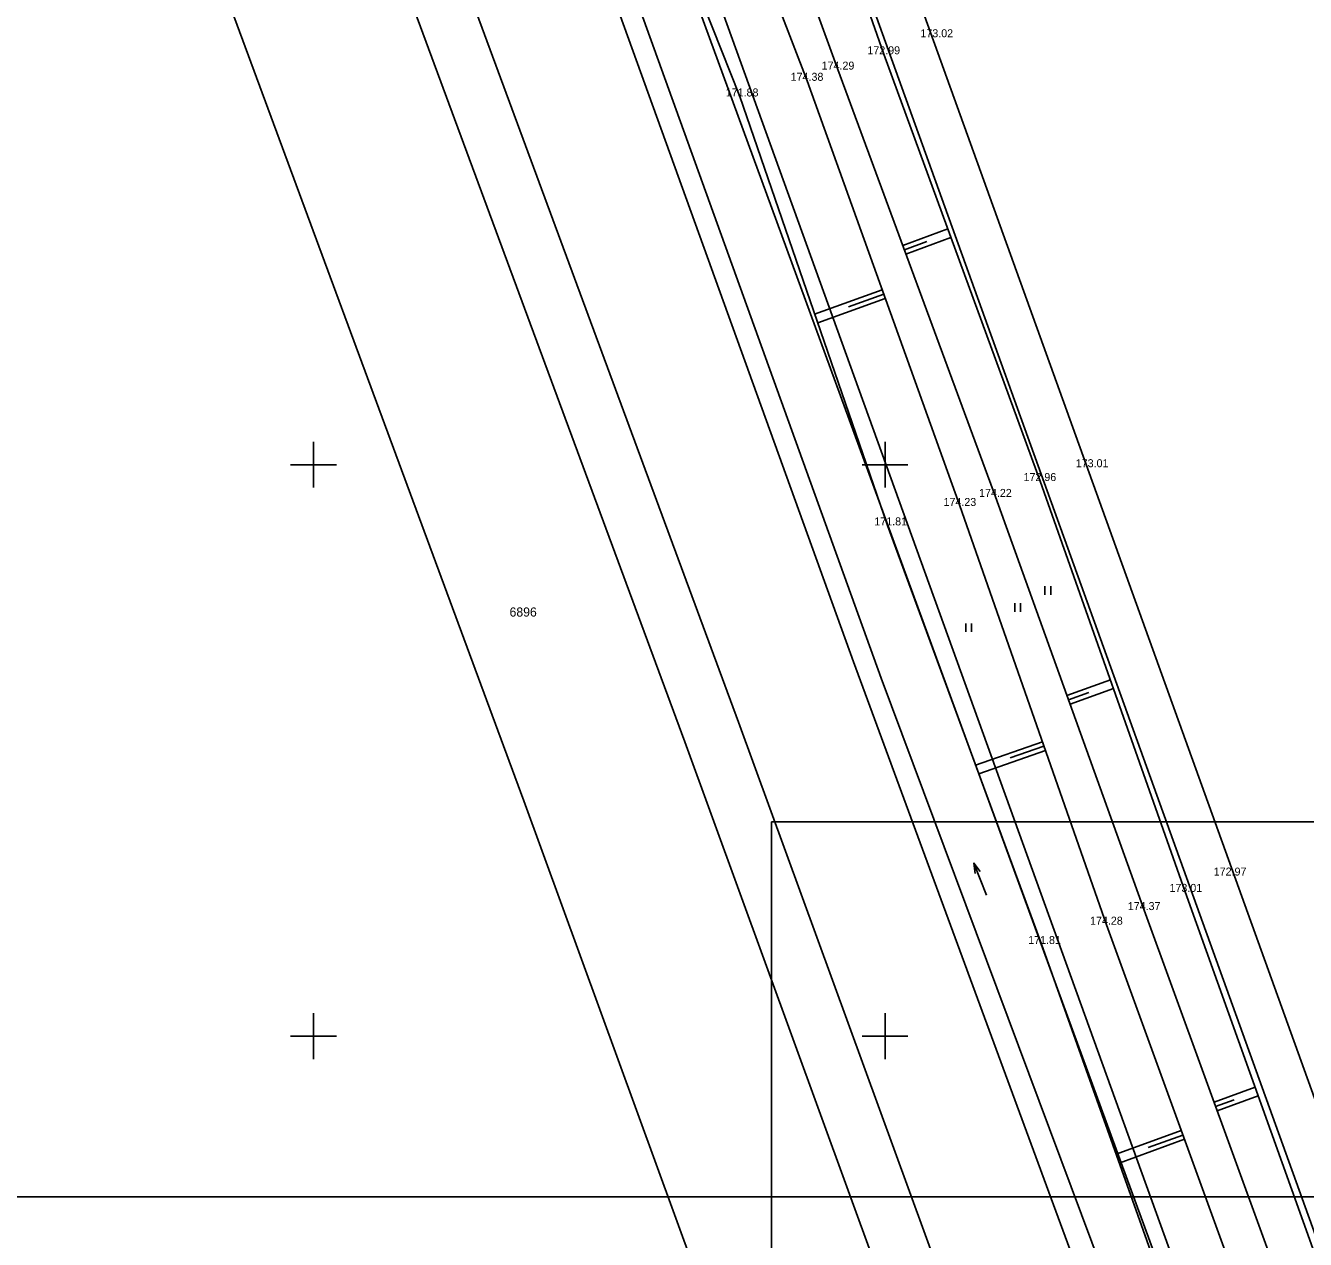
# Model space of a CAD drawing. Extents: x -612546 to -611926, y -1201932 to -1200444.
# Drawn here: x -612425.2 to -612313.2, y -1200867.8 to -1200761.6 of the extents above; entities that cross this region are included whole.
import ezdxf

# ---------------------------------------------------------------- set-up
doc = ezdxf.new("R2010")
doc.units = 0
for name, color, linetype in [('14 hrana pata svahu', 7, 'Continuous'), ('15 šrafy', 7, 'Continuous'), ('61 legenda křížky', 7, 'Continuous'), ('Hranice parcel', 7, 'Continuous'), ('Parcelní čísla', 7, 'Continuous'), ('Vnitřní kresba', 7, 'Continuous'), ('Vrstva 36', 7, 'Continuous'), ('Vrstva 45', 7, 'Continuous'), ('Vrstva 63', 7, 'Continuous'), ('výška bodu', 7, 'Continuous')]:
    doc.layers.add(name, color=color, linetype=linetype)

msp = doc.modelspace()

# ---------------------------------------------------------------- linework, layer by layer
at = {"layer": '14 hrana pata svahu'}
for points in [[(-612314.18, -1200875.11), (-612327.34, -1200838.97), (-612340.35, -1200802.82), (-612354.12, -1200765.43), (-612365.98, -1200732.87), (-612379.97, -1200693.65), (-612390.48, -1200664.58), (-612404.32, -1200627.17), (-612417.23, -1200591.7), (-612430.62, -1200555.12), (-612438.2, -1200533.09), (-612444.43, -1200520.21), (-612457.3, -1200503.64), (-612467.57, -1200490.07), (-612474.64, -1200478.9), (-612480.36, -1200469.57)], [(-612115.84, -1201111.42), (-612142.3, -1201080.92), (-612162.58, -1201054.92), (-612187.22, -1201025.94), (-612211.45, -1200996.73), (-612237.71, -1200968.13), (-612275.47, -1200925.26), (-612297.25, -1200898.18), (-612305.42, -1200888.34), (-612310.59, -1200874.11), (-612323.74, -1200837.38), (-612336.44, -1200801.43), (-612350.12, -1200764.09), (-612361.57, -1200731.35), (-612377.95, -1200692.77), (-612388.38, -1200663.69), (-612401.66, -1200625.89), (-612414.44, -1200590.59), (-612427.78, -1200553.92), (-612436.33, -1200532.1), (-612442.76, -1200519.02), (-612455.83, -1200502.43), (-612463.71, -1200487.36), (-612471.87, -1200478.15)], [(-612323.51, -1200877.98), (-612336.33, -1200841.94), (-612349.79, -1200805.31), (-612362.71, -1200767.78), (-612375.47, -1200735.58), (-612389.68, -1200697.07), (-612400.23, -1200666.93), (-612413.57, -1200629.83), (-612426, -1200594.78), (-612439.47, -1200557.74), (-612446.83, -1200536.72), (-612452.68, -1200524.51), (-612464.9, -1200509.43), (-612478.9, -1200492.91), (-612482.95, -1200488.23)], [(-612103.83, -1201136.8), (-612121.3, -1201116.23), (-612147.17, -1201085.43), (-612168.95, -1201059.31), (-612192.84, -1201031.05), (-612217.78, -1201001.78), (-612242.41, -1200972.81), (-612279.4, -1200929.44), (-612302.66, -1200902.78), (-612311.18, -1200891.48), (-612317.69, -1200875.87), (-612330.64, -1200840.25), (-612343.46, -1200803.61), (-612356.83, -1200766.41), (-612369.51, -1200733.46), (-612383.93, -1200694.82), (-612394.68, -1200665.1), (-612407.78, -1200627.56), (-612420.74, -1200592.57), (-612433.93, -1200555.79), (-612441.34, -1200534.1), (-612447.31, -1200522.04), (-612459.97, -1200505.78), (-612472.95, -1200489.44)]]:
    msp.add_lwpolyline(points, dxfattribs=at)
at = {"layer": '15 šrafy'}
for p, q in [((-612344.52, -1200779.37), (-612348.45, -1200780.82)), ((-612346.34, -1200780.47), (-612348.31, -1200781.19)), ((-612344.25, -1200780.12), (-612348.18, -1200781.57)), ((-612356.16, -1200786.82), (-612350.26, -1200784.7)), ((-612353.19, -1200786.18), (-612350.12, -1200785.08)), ((-612355.89, -1200787.58), (-612349.99, -1200785.45)), ((-612330.29, -1200818.83), (-612334.09, -1200820.2)), ((-612330.02, -1200819.59), (-612333.82, -1200820.96)), ((-612332.17, -1200819.94), (-612333.96, -1200820.58)), ((-612342.08, -1200826.29), (-612336.24, -1200824.25)), ((-612341.8, -1200827.04), (-612335.98, -1200825)), ((-612339.05, -1200825.65), (-612336.11, -1200824.62)), ((-612317.62, -1200854.47), (-612321.22, -1200855.78)), ((-612319.46, -1200855.57), (-612321.08, -1200856.16)), ((-612317.35, -1200855.23), (-612320.94, -1200856.54)), ((-612329.78, -1200860.34), (-612324.09, -1200858.27)), ((-612329.52, -1200861.1), (-612323.82, -1200859.02)), ((-612326.98, -1200859.75), (-612323.95, -1200858.65))]:
    msp.add_line(p, q, dxfattribs=at)
at = {"layer": '61 legenda křížky'}
for p, q in [((-612400, -1200802), (-612400, -1200798)), ((-612350, -1200802), (-612350, -1200798)), ((-612402, -1200800), (-612398, -1200800)), ((-612352, -1200800), (-612348, -1200800)), ((-612400, -1200852), (-612400, -1200848)), ((-612350, -1200852), (-612350, -1200848)), ((-612402, -1200850), (-612398, -1200850)), ((-612352, -1200850), (-612348, -1200850))]:
    msp.add_line(p, q, dxfattribs=at)
at = {"layer": 'Hranice parcel'}
for points in [[(-612492.54, -1200475.45), (-612489.15, -1200479.9), (-612487.29, -1200482.34), (-612470.55, -1200499.86), (-612454.58, -1200517.89), (-612449.12, -1200526.98), (-612444.88, -1200537.01), (-612400.71, -1200658.68), (-612382.76, -1200708.97), (-612320.94, -1200880.21), (-612316.28, -1200891.06), (-612307.37, -1200903.62), (-612259.67, -1200958.71), (-612214.29, -1201012.03), (-612172.62, -1201060.98), (-612120.7, -1201123.05), (-612073.85, -1201178.4), (-612068.4, -1201184.83), (-612055.42, -1201199.11), (-612044.78, -1201213.9), (-612040.42, -1201224.33), (-612036.87, -1201232.26)], [(-612053.63, -1201234.04), (-612049.72, -1201229.74), (-612051.31, -1201220.57), (-612058.28, -1201208.42), (-612073.89, -1201189.58), (-612079.31, -1201183.16), (-612173.25, -1201072.99), (-612266.53, -1200963.98), (-612308.11, -1200916.05), (-612320.05, -1200901.46), (-612326.37, -1200888.91), (-612352.76, -1200817.26), (-612383.45, -1200732.24), (-612424.46, -1200618.96), (-612450.75, -1200547.77), (-612455.75, -1200534.91), (-612462.05, -1200524.68), (-612490.01, -1200492.58), (-612497.19, -1200482.99)], [(-612504.85, -1200495.41), (-612492.66, -1200506.93), (-612476.27, -1200525), (-612462.43, -1200549.41), (-612435.01, -1200623.69), (-612394.62, -1200736.44), (-612362.83, -1200822.52), (-612336.91, -1200893.7), (-612329.46, -1200906.86), (-612317.29, -1200922.46), (-612274.72, -1200972.15), (-612181.97, -1201080.59), (-612092.56, -1201185.28), (-612096.16, -1201188.77)], [(-612098.55, -1201185.97), (-612185.77, -1201083.84), (-612278.52, -1200975.4), (-612321.16, -1200925.63), (-612333.63, -1200909.64), (-612341.47, -1200895.8), (-612367.52, -1200824.24), (-612399.32, -1200738.15), (-612439.71, -1200625.4), (-612466.98, -1200551.52), (-612480.35, -1200527.95), (-612496.23, -1200510.43), (-612507.54, -1200499.75)], [(-612424.14, -1200544.19), (-612385.56, -1200652.97), (-612376.97, -1200665.68), (-612365.31, -1200671.92), (-612359.59, -1200681.01), (-612363.6, -1200702.67), (-612362.5, -1200716.42), (-612304.9, -1200876.31), (-612299.88, -1200886.48), (-612289.63, -1200899.21), (-612225.19, -1200972.6)], [(-612480.63, -1200557.86), (-612453.81, -1200630.53), (-612413.42, -1200743.28), (-612381.61, -1200829.41), (-612355.13, -1200902.11), (-612346.14, -1200918), (-612332.78, -1200935.12), (-612289.91, -1200985.15), (-612197.17, -1201093.58), (-612109.96, -1201195.71)], [(-612367.63, -1200702.46), (-612366.44, -1200717.27), (-612308.59, -1200877.88), (-612303.27, -1200888.65), (-612292.69, -1200901.79), (-612203.37, -1201003.51), (-612163.72, -1201050.75), (-612139.89, -1201080.24), (-612084.23, -1201147.54), (-612068.31, -1201163.86)]]:
    msp.add_lwpolyline(points, dxfattribs=at)
at = {"layer": 'Vnitřní kresba'}
msp.add_line((-612380.36, -1200721.61), (-612321.45, -1200882.64), dxfattribs=at)
msp.add_lwpolyline([(-612077.99, -1201182.01), (-612172.2, -1201072.72), (-612264.55, -1200963.36), (-612306.48, -1200914.97), (-612319.15, -1200900.26), (-612324.5, -1200887.86), (-612350.35, -1200818.69), (-612381.6, -1200731.97), (-612422.84, -1200618.87), (-612449.81, -1200544.11), (-612465.28, -1200517.45), (-612482.79, -1200495.64), (-612497.19, -1200482.99)], dxfattribs=at)
at = {"layer": 'Vrstva 36'}
for p, q in [((-612336.01, -1200811.39), (-612336.01, -1200810.64)), ((-612335.51, -1200811.39), (-612335.51, -1200810.64)), ((-612338.66, -1200812.86), (-612338.66, -1200812.11)), ((-612338.16, -1200812.86), (-612338.16, -1200812.11)), ((-612342.93, -1200814.63), (-612342.93, -1200813.88)), ((-612342.43, -1200814.63), (-612342.43, -1200813.88))]:
    msp.add_line(p, q, dxfattribs=at)
at = {"layer": 'Vrstva 45'}
msp.add_line((-612341.12, -1200837.65), (-612342.23, -1200834.86), dxfattribs=at)
msp.add_lwpolyline([(-612342.12, -1200835.76), (-612342.23, -1200834.86), (-612341.69, -1200835.59)], dxfattribs=at)
at = {"layer": 'Vrstva 63'}
for p, q in [((-612359.93, -1201251.26), (-612359.93, -1200831.26)), ((-612359.93, -1200831.26), (-612062.93, -1200831.26)), ((-612232.3, -1200864.06), (-612529.3, -1200864.06))]:
    msp.add_line(p, q, dxfattribs=at)

# ---------------------------------------------------------------- texts
at = {"layer": 'Parcelní čísla'}
msp.add_text('6896', height=0.8, dxfattribs=at).set_placement((-612382.85, -1200813.29))
at = {"layer": 'výška bodu'}
for s, p in [('173.02', (-612346.91, -1200762.6)), ('172.99', (-612351.55, -1200764.09)), ('174.29', (-612355.55, -1200765.43)), ('174.38', (-612358.26, -1200766.41)), ('171.88', (-612363.94, -1200767.78)), ('173.01', (-612333.32, -1200800.22)), ('172.96', (-612337.89, -1200801.43)), ('174.23', (-612344.89, -1200803.61)), ('174.22', (-612341.78, -1200802.82)), ('171.81', (-612350.94, -1200805.31)), ('172.97', (-612321.25, -1200835.95)), ('173.01', (-612325.12, -1200837.38)), ('174.37', (-612328.77, -1200838.97)), ('174.28', (-612332.07, -1200840.25)), ('171.81', (-612337.48, -1200841.94))]:
    msp.add_text(s, height=0.7, dxfattribs=at).set_placement(p)

doc.saveas('drawing.dxf')
